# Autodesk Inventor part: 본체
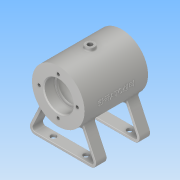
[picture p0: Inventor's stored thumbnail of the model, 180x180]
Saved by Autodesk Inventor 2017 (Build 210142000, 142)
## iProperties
Part Number: 본체
Material: 알루미늄 6061
Document SubType Name: Modeling
Designer: Administrator
Density: 2.7 g/cm^3
Appearance: 알루미늄 - 평지
Mass: 310.254 g
Surface Area: 354.969 cm^2
Volume: 114.909 cm^3
Author: Administrator
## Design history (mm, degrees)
sketch "스케치1"
  geometry: C1 r 29 at (0, 0); 1 further point
  constraints: 1 centre point, 1 coincident
  dimensions: "d0" = 58 diameter of C1
extrude "돌출1" new body sketch "스케치1" stored distance "d1" = 70; taper "d2" = 0 deg
sketch "스케치2"
  geometry: C1 r 16 at (0, 0); 1 further point
  constraints: 1 centre point, 1 coincident
  dimensions: "d3" = 32 diameter of C1
extrude "돌출2" cut sketch "스케치2" distance "d4" = 12; taper "d5" = 0 deg
sketch "스케치3"
  geometry: C1 r 14 at (0, 0); 1 further point
  constraints: 1 centre point, 1 coincident
  dimensions: "d6" = 28 diameter of C1
extrude "돌출3" cut sketch "스케치3" distance "d7" = 2; taper "d8" = 0 deg
sketch "스케치4"
  geometry: C1 r 21 at (0, 0); 1 further point
  constraints: 1 centre point, 1 coincident
  dimensions: "d9" = 42 diameter of C1
extrude "돌출4" cut sketch "스케치4" stored distance "d10" = 42; taper "d11" = 0 deg
node "작업 평면1"
sketch "스케치5"
  geometry: L1 (-40, -55)-(40, -55); L2 (40, -55)-(22.743, -17.993); L3 (-40, -55)-(-22.743, -17.993); L4 (0, -55)-(0, -29); C1 r 16 at (0, 0) reference; A1 r 29 centre (0, 0) between (22.743, -17.993) and (-22.743, -17.993) reference; A2 r 29 centre (0, 0) between (-22.743, -17.993) and (22.743, -17.993); A3 r 29 centre (0, 0) between (22.743, -17.993) and (0.836, 28.988); A4 r 29 centre (0, 0) between (0.836, 28.988) and (-22.743, -17.993); 1 further point
  constraints: 10 point on circle, 8 end point, 3 centre point, 1 coincident, 1 horizontal, 1 midpoint, 1 point on line, 1 vertical, 1 vertical alignment
  dimensions: "d13" = 80 distance of L1.start L1.end; "d14" = 55 distance from line of point (0, 0) L1; "d15" = 65 deg angle of L1 L2; "d16" = 65 deg angle of L1 L3
extrude "돌출5" join sketch "스케치5" distance "d18" = 12; taper "d19" = 0 deg
sketch "스케치6"
  geometry: L1 (-40, -55)-(-22.743, -17.993) reference; L2 (22.743, -17.993)-(40, -55) reference; L3 (40, -55)-(-40, -55) reference; L4 (-35.291, -52)-(35.291, -52); L5 (35.291, -52)-(20.574, -20.438); L6 (-35.291, -52)-(-20.574, -20.438); L7 (0, -52)-(0, -29); C1 r 16 at (0, 0) reference; A1 r 29 centre (0, 0) between (-22.743, -17.993) and (22.743, -17.993) reference; A2 r 29 centre (0, 0) between (22.743, -17.993) and (-22.743, -17.993) reference; A3 r 29 centre (0, 0) between (-22.743, -17.993) and (22.743, -17.993) reference; A4 r 29 centre (0, 0) between (22.743, -17.993) and (-20.574, -20.438); A5 r 29 centre (0, 0) between (20.574, -20.438) and (22.743, -17.993); A6 r 29 centre (0, 0) between (-20.574, -20.438) and (20.574, -20.438); 1 further point
  constraints: 13 point on circle, 9 end point, 3 centre point, 3 parallel, 1 coincident, 1 horizontal, 1 midpoint
  dimensions: "d21" = 3 distance between parallel lines of L1 L6; "d22" = 3 distance between parallel lines of L3 L4; "d23" = 3 distance between parallel lines of L2 L5
extrude "돌출6" cut sketch "스케치6" distance "d24" = 12; taper "d25" = 0 deg
node "작업 평면2"
sketch "스케치7"
  geometry: C1 r 5 at (0, 0); 1 further point
  constraints: 1 centre point, 1 coincident
  dimensions: "d27" = 10 diameter of C1
extrude "돌출7" join sketch "스케치7" stored distance "d28" = 12; taper "d29" = 0 deg
sketch "스케치8"
  geometry: 2 further points
  constraints: 1 coincident
hole "구멍1" sketch "스케치8" at (0, 0) diameter "d30" = 5.188; stored, may be unused: countersink angle "d34" = 90 deg, drill point angle "d36" = 118 deg; dims "d31" = 6, "d32" = 4, "d33" = 2, "d35" = 8
sketch "스케치9"
  geometry: C1 r 2.594 at (0, 0) reference; C2 r 5 at (0, 0) reference; C3 r 1.5 at (0, 0); 1 further point
  constraints: 1 centre point, 1 coincident
  dimensions: "d37" = 3 diameter of C3
extrude "돌출8" cut sketch "스케치9" distance "d38" = 20.75; taper "d39" = 0 deg
node "작업 평면4"
  node "작업 평면3"
sketch "스케치10"
  geometry: C1 r 6 at (0, 0); 1 further point
  constraints: 1 centre point, 1 coincident
  dimensions: "d42" = 12 diameter of C1
extrude "돌출9" join sketch "스케치10" stored distance "d43" = 20.75; taper "d44" = 0 deg
sketch "스케치11"
  geometry: 2 further points
  constraints: 1 coincident
hole "구멍2" sketch "스케치11" at (0, 0) diameter "d45" = 5.188; stored, may be unused: countersink angle "d49" = 90 deg, drill point angle "d51" = 118 deg; dims "d46" = 12, "d47" = 4, "d48" = 2, "d50" = 23
sketch "스케치12" dims "d52" = 42
  geometry: 3 further points
  constraints: 2 vertical alignment, 1 coincident, 2 other
hole "구멍3" sketch "스케치12" at (0, 21) diameter "d53" = 3.242; stored, may be unused: countersink angle "d57" = 90 deg, drill point angle "d59" = 118 deg; dims "d54" = 8, "d55" = 4, "d56" = 2, "d58" = 10
sketch "스케치13"
  geometry: L1 (0, -48)-(80, -48) reference; L2 (80, -48)-(80, -60) reference; L3 (80, -60)-(0, -60) reference; L4 (0, -60)-(0, -48) reference; L5 (0, 0)-(80, 0) reference; L6 (80, 0)-(80, -12) reference; L7 (80, -12)-(0, -12) reference; L8 (0, -12)-(0, 0) reference; L9 (41.621, -5)-(41.621, 5) reference; L10 (41.621, 0)-(41.621, -60); L11 (41.621, -65)-(41.621, -55) reference; C1 r 3 at (59.621, -6); C2 r 3 at (23.621, -6); C3 r 3 at (59.621, -54); C4 r 3 at (23.621, -54); 1 further point
  constraints: 4 centre point, 2 end point, 2 horizontal alignment, 2 midpoint, 2 vertical alignment
  dimensions: "d63" = 6 diameter of C1; "d64" = 6 diameter of C2; "d65" = 6 distance from line of L5 C1.centre; "d66" = 6 diameter of C3; "d67" = 6 diameter of C4; "d68" = 48 distance of C1.centre C3.centre; "d69" = 36 distance of C1.centre C2.centre; "d70" = 18 horizontal distance of L9.start C2.centre
extrude "돌출10" cut sketch "스케치13" distance "d71" = 3; taper "d72" = 0 deg
chamfer "모따기1" distance "d73" = 1; stored, may be unused: second distance "d74" = 2, angle "d75" = 45 deg
fillet "모깎기1" dims "d76" = 1, "d77" = 0.3, "d78" = 6
fillet "모깎기2" dims "d79" = 0.5
fillet "모깎기3" dims "d80" = 3
fillet "모깎기4" dims "d81" = 0.5
fillet "모깎기5" dims "d82" = 3
node "작업 평면5"
sketch "스케치14"
  geometry: L1 (29, -35)-(29, 35) reference; L2 (29, 35)-(-29, 35) reference; 2 further points
  constraints: 1 other
  dimensions: "d84" = 29 distance from line of point (0, 0) L1; "d85" = 35 distance from line of L2 point (0, 0)
feature "엠보싱1" sketch "스케치14" dims "d86" = 0.5, "d87" = 0
node "솔리드1"
mirror "미러1"
mirror "미러2"
pattern_circular "원형 패턴1" dims angle "d61" = 360 deg
mirror "미러3"
node "절단 모서리 투영1"
node "절단 모서리 투영2"
node "절단 모서리 투영3"
node "절단 모서리 투영4"
other parameters: "d12" = -5, "d26" = 32, "d40" = -20 deg, "d41" = -32, "d83" = 46.75
